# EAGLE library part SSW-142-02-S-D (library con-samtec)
THROUGH-HOLE .025" SQ POST SOCKET Source: Samtec SSW.pdf
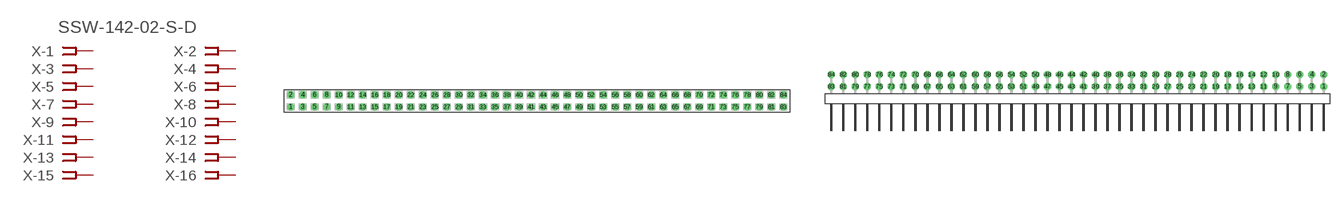
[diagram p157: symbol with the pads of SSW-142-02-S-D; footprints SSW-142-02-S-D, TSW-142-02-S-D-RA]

Designator prefix X; gates -1=FPINV -2=FPIN -3=FPIN -4=FPIN -5=FPIN -6=FPIN -7=FPIN -8=FPIN -9=FPIN -10=FPIN -11=FPIN -12=FPIN -13=FPIN -14=FPIN -15=FPIN -16=FPIN -17=FPIN -18=FPIN -19=FPIN -20=FPIN -21=FPIN -22=FPIN -23=FPIN -24=FPIN -25=FPIN -26=FPIN -27=FPIN -28=FPIN -29=FPIN -30=FPIN -31=FPIN -32=FPIN -33=FPIN -34=FPIN -35=FPIN -36=FPIN -37=FPIN -38=FPIN -39=FPIN -40=FPIN -41=FPIN -42=FPIN -43=FPIN -44=FPIN -45=FPIN -46=FPIN -47=FPIN -48=FPIN -49=FPIN -50=FPIN -51=FPIN -52=FPIN -53=FPIN -54=FPIN -55=FPIN -56=FPIN -57=FPIN -58=FPIN -59=FPIN -60=FPIN -61=FPIN -62=FPIN -63=FPIN -64=FPIN -65=FPIN -66=FPIN -67=FPIN -68=FPIN -69=FPIN -70=FPIN -71=FPIN -72=FPIN -73=FPIN -74=FPIN -75=FPIN -76=FPIN -77=FPIN -78=FPIN -79=FPIN -80=FPIN -81=FPIN -82=FPIN -83=FPIN -84=FPIN

## SSW-142-02-S-D (MPN: SSW-142-02-S-D; OC_FARNELL: unknown; OC_NEWARK: 11P9979)  [SSW-142-02-S-D]
1  -1:1  pas
2  -2:1  pas
3  -3:1  pas
4  -4:1  pas
5  -5:1  pas
6  -6:1  pas
7  -7:1  pas
8  -8:1  pas
9  -9:1  pas
10  -10:1  pas
11  -11:1  pas
12  -12:1  pas
13  -13:1  pas
14  -14:1  pas
15  -15:1  pas
16  -16:1  pas
17  -17:1  pas
18  -18:1  pas
19  -19:1  pas
20  -20:1  pas
21  -21:1  pas
22  -22:1  pas
23  -23:1  pas
24  -24:1  pas
25  -25:1  pas
26  -26:1  pas
27  -27:1  pas
28  -28:1  pas
29  -29:1  pas
30  -30:1  pas
31  -31:1  pas
32  -32:1  pas
33  -33:1  pas
34  -34:1  pas
35  -35:1  pas
36  -36:1  pas
37  -37:1  pas
38  -38:1  pas
39  -39:1  pas
40  -40:1  pas
41  -41:1  pas
42  -42:1  pas
43  -43:1  pas
44  -44:1  pas
45  -45:1  pas
46  -46:1  pas
47  -47:1  pas
48  -48:1  pas
49  -49:1  pas
50  -50:1  pas
51  -51:1  pas
52  -52:1  pas
53  -53:1  pas
54  -54:1  pas
55  -55:1  pas
56  -56:1  pas
57  -57:1  pas
58  -58:1  pas
59  -59:1  pas
60  -60:1  pas
61  -61:1  pas
62  -62:1  pas
63  -63:1  pas
64  -64:1  pas
65  -65:1  pas
66  -66:1  pas
67  -67:1  pas
68  -68:1  pas
69  -69:1  pas
70  -70:1  pas
71  -71:1  pas
72  -72:1  pas
73  -73:1  pas
74  -74:1  pas
75  -75:1  pas
76  -76:1  pas
77  -77:1  pas
78  -78:1  pas
79  -79:1  pas
80  -80:1  pas
81  -81:1  pas
82  -82:1  pas
83  -83:1  pas
84  -84:1  pas

## SSW-142-02-S-D-RA (MPN: SSW-142-02-S-D-RA; OC_FARNELL: unknown; OC_NEWARK: 11P9980)  [TSW-142-02-S-D-RA]
Pads as for SSW-142-02-S-D

## Footprint SSW-142-02-S-D (pad centres in mm)
THROUGH-HOLE .025" SQ POST SOCKET Source: Samtec SSW.pdf
drill 1 pad 1.5 octagon: 1 -52.07,-1.27; 2 -52.07,1.27; 3 -49.53,-1.27; 4 -49.53,1.27; 5 -46.99,-1.27; 6 -46.99,1.27; 7 -44.45,-1.27; 8 -44.45,1.27; 9 -41.91,-1.27; 10 -41.91,1.27; 11 -39.37,-1.27; 12 -39.37,1.27; 13 -36.83,-1.27; 14 -36.83,1.27; 15 -34.29,-1.27; 16 -34.29,1.27; 17 -31.75,-1.27; 18 -31.75,1.27; 19 -29.21,-1.27; 20 -29.21,1.27; 21 -26.67,-1.27; 22 -26.67,1.27; 23 -24.13,-1.27; 24 -24.13,1.27; 25 -21.59,-1.27; 26 -21.59,1.27; 27 -19.05,-1.27; 28 -19.05,1.27; 29 -16.51,-1.27; 30 -16.51,1.27; 31 -13.97,-1.27; 32 -13.97,1.27; 33 -11.43,-1.27; 34 -11.43,1.27; 35 -8.89,-1.27; 36 -8.89,1.27; 37 -6.35,-1.27; 38 -6.35,1.27; 39 -3.81,-1.27; 40 -3.81,1.27; 41 -1.27,-1.27; 42 -1.27,1.27; 43 1.27,-1.27; 44 1.27,1.27; 45 3.81,-1.27; 46 3.81,1.27; 47 6.35,-1.27; 48 6.35,1.27; 49 8.89,-1.27; 50 8.89,1.27; 51 11.43,-1.27; 52 11.43,1.27; 53 13.97,-1.27; 54 13.97,1.27; 55 16.51,-1.27; 56 16.51,1.27; 57 19.05,-1.27; 58 19.05,1.27; 59 21.59,-1.27; 60 21.59,1.27; 61 24.13,-1.27; 62 24.13,1.27; 63 26.67,-1.27; 64 26.67,1.27; 65 29.21,-1.27; 66 29.21,1.27; 67 31.75,-1.27; 68 31.75,1.27; 69 34.29,-1.27; 70 34.29,1.27; 71 36.83,-1.27; 72 36.83,1.27; 73 39.37,-1.27; 74 39.37,1.27; 75 41.91,-1.27; 76 41.91,1.27; 77 44.45,-1.27; 78 44.45,1.27; 79 46.99,-1.27; 80 46.99,1.27; 81 49.53,-1.27; 82 49.53,1.27; 83 52.07,-1.27; 84 52.07,1.27

## Footprint TSW-142-02-S-D-RA (pad centres in mm)
THROUGH-HOLE .025" SQ POST HEADER Source: Samtec TSW.pdf
drill 1 pad 1.5 octagon: 1 52.07,1.524; 2 52.07,4.064; 3 49.53,1.524; 4 49.53,4.064; 5 46.99,1.524; 6 46.99,4.064; 7 44.45,1.524; 8 44.45,4.064; 9 41.91,1.524; 10 41.91,4.064; 11 39.37,1.524; 12 39.37,4.064; 13 36.83,1.524; 14 36.83,4.064; 15 34.29,1.524; 16 34.29,4.064; 17 31.75,1.524; 18 31.75,4.064; 19 29.21,1.524; 20 29.21,4.064; 21 26.67,1.524; 22 26.67,4.064; 23 24.13,1.524; 24 24.13,4.064; 25 21.59,1.524; 26 21.59,4.064; 27 19.05,1.524; 28 19.05,4.064; 29 16.51,1.524; 30 16.51,4.064; 31 13.97,1.524; 32 13.97,4.064; 33 11.43,1.524; 34 11.43,4.064; 35 8.89,1.524; 36 8.89,4.064; 37 6.35,1.524; 38 6.35,4.064; 39 3.81,1.524; 40 3.81,4.064; 41 1.27,1.524; 42 1.27,4.064; 43 -1.27,1.524; 44 -1.27,4.064; 45 -3.81,1.524; 46 -3.81,4.064; 47 -6.35,1.524; 48 -6.35,4.064; 49 -8.89,1.524; 50 -8.89,4.064; 51 -11.43,1.524; 52 -11.43,4.064; 53 -13.97,1.524; 54 -13.97,4.064; 55 -16.51,1.524; 56 -16.51,4.064; 57 -19.05,1.524; 58 -19.05,4.064; 59 -21.59,1.524; 60 -21.59,4.064; 61 -24.13,1.524; 62 -24.13,4.064; 63 -26.67,1.524; 64 -26.67,4.064; 65 -29.21,1.524; 66 -29.21,4.064; 67 -31.75,1.524; 68 -31.75,4.064; 69 -34.29,1.524; 70 -34.29,4.064; 71 -36.83,1.524; 72 -36.83,4.064; 73 -39.37,1.524; 74 -39.37,4.064; 75 -41.91,1.524; 76 -41.91,4.064; 77 -44.45,1.524; 78 -44.45,4.064; 79 -46.99,1.524; 80 -46.99,4.064; 81 -49.53,1.524; 82 -49.53,4.064; 83 -52.07,1.524; 84 -52.07,4.064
